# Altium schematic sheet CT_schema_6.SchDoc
size 254 x 245 mm
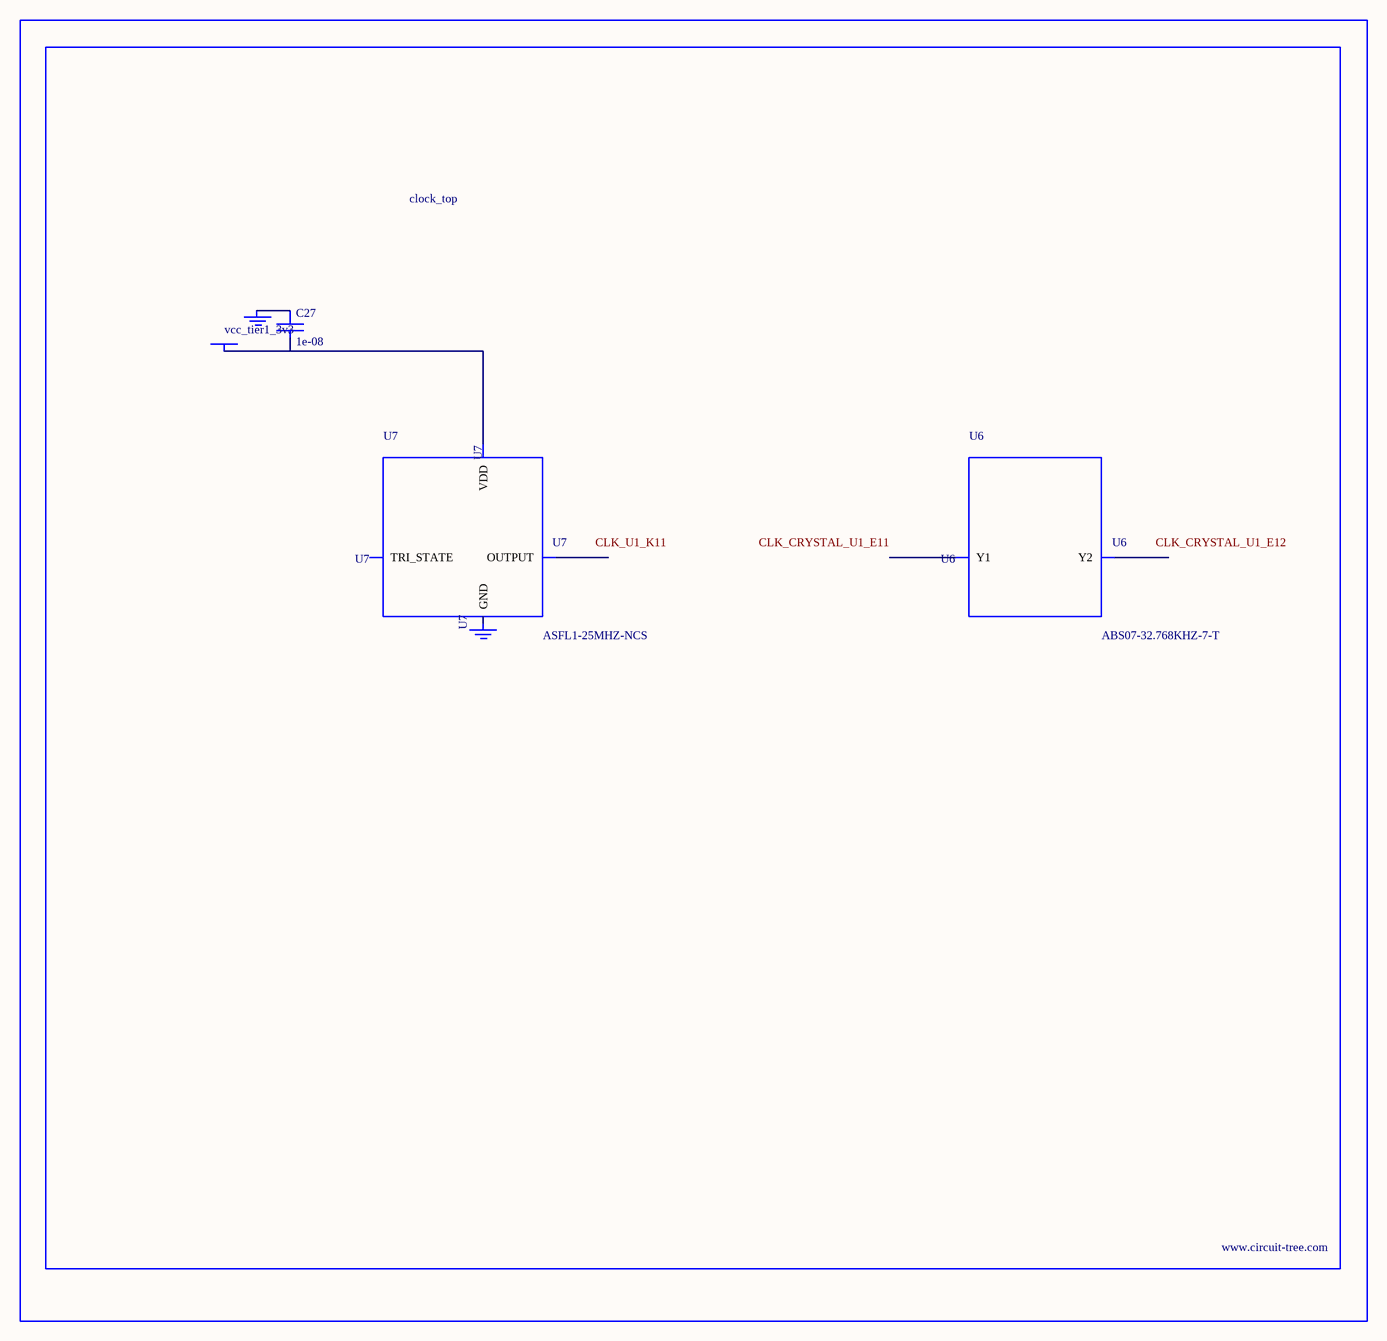
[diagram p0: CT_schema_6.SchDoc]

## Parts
BORDER5  (no value)
C27  1e-08  [C0402]
GND_INSTANCE_5_0  (no value)
GND_INSTANCE_5_1  (no value)
POWER_INSTANCE_5_0  vcc_tier1_3v3
U6  ABS07-32.768KHZ-7-T  [ABS07-32.768KHZ-7-T]
U7  ASFL1-25MHZ-NCS  [ASFL1]

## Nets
NetC27_1: C27.1 GND_INSTANCE_5_0.0(GND)
NetC27_2: C27.2 POWER_INSTANCE_5_0.0(PWR) U7.4(VDD)

Not connected (* = marked no-connect by the designer): GND_INSTANCE_5_1 0(GND); U6 1(Y1) 2(Y2); U7 1(TRI_STATE) 2(GND) 3(OUTPUT)

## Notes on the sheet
- Labels drawn without touching a wire or pin: CLK_CRYSTAL_U1_E11, CLK_CRYSTAL_U1_E12, CLK_U1_K11

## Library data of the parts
BORDER5 = BORDER_PAGE5
C27 = C0402C103K3RAC
GND_INSTANCE_5_0 GND_INSTANCE_5_1 = GND
POWER_INSTANCE_5_0 = PWR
